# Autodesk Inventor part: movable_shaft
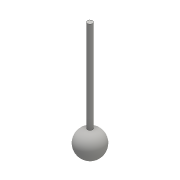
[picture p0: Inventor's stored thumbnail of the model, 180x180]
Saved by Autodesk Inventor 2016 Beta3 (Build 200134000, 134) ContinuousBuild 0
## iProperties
Created: 2016-03
Part Number: movable_shaft
Material: Generic
Document SubType Name: Modeling
Designer: Gaurav
Density: 1 g/cm^3
Appearance: Default
Author: Gaurav
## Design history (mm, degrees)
sketch "Sketch1"
  geometry: L1 (-12.5, 0)-(12.5, 0); A1 r 12.5 centre (0, 0) between (12.5, 0) and (-12.5, 0); 1 further point
  constraints: 2 end point, 2 point on circle, 1 centre point, 1 coincident, 1 horizontal
  dimensions: "d0" = 25 diameter of A1
revolve "Revolution1" sketch "Sketch1" stored, may be unused: angle "d1" = 90 deg
sketch "Sketch2"
  geometry: C1 r 2.5 at (0, 0); 1 further point
  constraints: 1 centre point, 1 coincident
  dimensions: "d2" = 5 diameter of C1
extrude "Extrusion1" join sketch "Sketch2" distance "d3" = 101; taper "d4" = 0 deg
body "Solid1"
